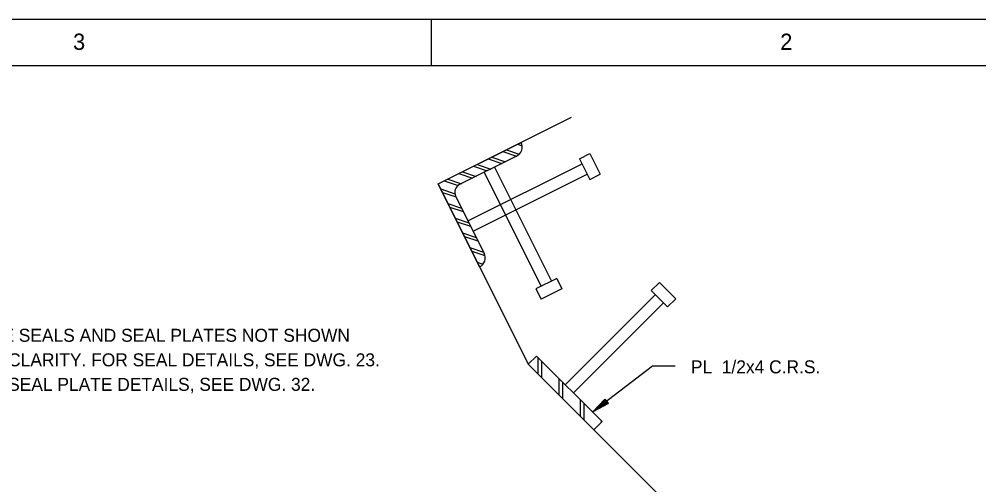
# Model space of a CAD drawing. Extents: x -0.2 to 13.5, y -0.2 to 9.5.
# Drawn here: x 6.602 to 10.051, y 7.66 to 9.333 of the extents above; entities that cross this region are included whole.
import ezdxf

# ---------------------------------------------------------------- set-up
doc = ezdxf.new("R2010")
doc.units = 0
for name, color, linetype in [('Level 1', 7, 'Continuous'), ('Level 2', 7, 'Continuous'), ('Level 25', 7, 'Continuous'), ('Level 3', 7, 'Continuous'), ('Level 36', 7, 'Continuous')]:
    doc.layers.add(name, color=color, linetype=linetype)

msp = doc.modelspace()

# ---------------------------------------------------------------- linework, layer by layer
at = {"layer": 'Level 1'}
msp.add_line((8.0833, 9.1667), (8.0833, 9.3333), dxfattribs=at)
for points in [[(0, 9.3333), (13.3333, 9.3333), (13.3333, 0), (0, 0)], [(0.5, 9.1667), (13.1667, 9.1667), (13.1667, 0.1667), (0.5, 0.1667)]]:
    msp.add_lwpolyline(points, close=True, dxfattribs=at)
at = {"layer": 'Level 2'}
for p, q in [((8.4673, 8.0574), (8.4673, 8.1163)), ((8.4806, 8.0441), (8.4806, 8.103)), ((8.5431, 7.9816), (8.5431, 8.0405)), ((8.5564, 7.9682), (8.5564, 8.0271)), ((8.6189, 7.9057), (8.6189, 7.9646)), ((8.6323, 7.8924), (8.6323, 7.9513)), ((8.6948, 7.8845), (8.6948, 7.8888))]:
    msp.add_line(p, q, dxfattribs=at)
at = {"layer": 'Level 25'}
for p, q in [((8.1077, 8.7411), (8.5876, 8.981)), ((8.1077, 8.7411), (8.5204, 8.9474)), ((8.3935, 8.884), (8.4093, 8.8787)), ((8.3935, 8.884), (8.4093, 8.8787)), ((8.288, 8.8313), (8.337, 8.815)), ((8.288, 8.8313), (8.337, 8.815)), ((8.3005, 8.8375), (8.3494, 8.8212)), ((8.3005, 8.8375), (8.3494, 8.8212)), ((8.3408, 8.8576), (8.3897, 8.8413)), ((8.3408, 8.8576), (8.3897, 8.8413)), ((8.3532, 8.8638), (8.3992, 8.8485)), ((8.3532, 8.8638), (8.3992, 8.8485)), ((8.6155, 8.8319), (8.6528, 8.8506)), ((8.6155, 8.8319), (8.6528, 8.8506)), ((8.2149, 8.6084), (8.6248, 8.8133)), ((8.2149, 8.6084), (8.6248, 8.8133)), ((8.2353, 8.8049), (8.2842, 8.7886)), ((8.2353, 8.8049), (8.2842, 8.7886)), ((8.2478, 8.8111), (8.2967, 8.7948)), ((8.2478, 8.8111), (8.2967, 8.7948)), ((8.3104, 8.8017), (8.5153, 8.3917)), ((8.3104, 8.8017), (8.5153, 8.3917)), ((8.1826, 8.7786), (8.2315, 8.7623)), ((8.1826, 8.7786), (8.2315, 8.7623)), ((8.1951, 8.7848), (8.244, 8.7685)), ((8.1951, 8.7848), (8.244, 8.7685)), ((8.2335, 8.5711), (8.6435, 8.776)), ((8.2335, 8.5711), (8.6435, 8.776)), ((8.2731, 8.783), (8.478, 8.3731)), ((8.2731, 8.783), (8.478, 8.3731)), ((8.6528, 8.7574), (8.69, 8.776)), ((8.6528, 8.7574), (8.69, 8.776)), ((8.1077, 8.7411), (8.4318, 8.0929)), ((8.1077, 8.7411), (8.4318, 8.0929)), ((8.1299, 8.7522), (8.1801, 8.7355)), ((8.1299, 8.7522), (8.1801, 8.7355)), ((8.1423, 8.7584), (8.1913, 8.7421)), ((8.1423, 8.7584), (8.1913, 8.7421)), ((8.1168, 8.7231), (8.1679, 8.706)), ((8.1168, 8.7231), (8.1679, 8.706)), ((8.123, 8.7106), (8.1719, 8.6943)), ((8.123, 8.7106), (8.1719, 8.6943)), ((8.1431, 8.6703), (8.192, 8.654)), ((8.1431, 8.6703), (8.192, 8.654)), ((8.1493, 8.6579), (8.1982, 8.6416)), ((8.1493, 8.6579), (8.1982, 8.6416)), ((8.1695, 8.6176), (8.2184, 8.6013)), ((8.1695, 8.6176), (8.2184, 8.6013)), ((8.1757, 8.6052), (8.2246, 8.5889)), ((8.1757, 8.6052), (8.2246, 8.5889)), ((8.1958, 8.5649), (8.2447, 8.5486)), ((8.1958, 8.5649), (8.2447, 8.5486)), ((8.202, 8.5525), (8.2509, 8.5362)), ((8.202, 8.5525), (8.2509, 8.5362)), ((8.2222, 8.5122), (8.2711, 8.4959)), ((8.2222, 8.5122), (8.2711, 8.4959)), ((8.2284, 8.4998), (8.2756, 8.484)), ((8.2284, 8.4998), (8.2756, 8.484)), ((8.2485, 8.4595), (8.2686, 8.4528)), ((8.2485, 8.4595), (8.2686, 8.4528)), ((8.2547, 8.4471), (8.2602, 8.4453)), ((8.2547, 8.4471), (8.2602, 8.4453)), ((8.5339, 8.401), (8.5526, 8.3638)), ((8.5339, 8.401), (8.5526, 8.3638)), ((8.8737, 8.3581), (8.9032, 8.3875)), ((8.8737, 8.3581), (8.9032, 8.3875)), ((8.9621, 8.3286), (8.9032, 8.3875)), ((8.9621, 8.3286), (8.9032, 8.3875)), ((8.4594, 8.3638), (8.478, 8.3265)), ((8.4594, 8.3638), (8.478, 8.3265)), ((8.9326, 8.2991), (8.8737, 8.3581)), ((8.9326, 8.2991), (8.8737, 8.3581)), ((8.5643, 8.0193), (8.8884, 8.3433)), ((8.5643, 8.0193), (8.8884, 8.3433)), ((8.5938, 7.9898), (8.9179, 8.3139)), ((8.5938, 7.9898), (8.9179, 8.3139)), ((8.9326, 8.2991), (8.9621, 8.3286)), ((8.9326, 8.2991), (8.9621, 8.3286)), ((8.4318, 8.0929), (8.4612, 8.1224)), ((8.4318, 8.0929), (8.4612, 8.1224)), ((8.6969, 7.8867), (8.4612, 8.1224)), ((8.6969, 7.8867), (8.4612, 8.1224)), ((8.4318, 8.0929), (9.4385, 7.0861)), ((8.6675, 7.8572), (8.6969, 7.8867)), ((8.6675, 7.8572), (8.6969, 7.8867))]:
    msp.add_line(p, q, dxfattribs=at)
at = {"layer": 'Level 3'}
for p, q in [((8.6637, 7.9219), (8.6637, 7.9219)), ((8.6775, 7.9325), (8.6775, 7.9325))]:
    msp.add_line(p, q, dxfattribs=at)
for points in [[(8.9594, 8.0856), (8.8776, 8.0856), (8.6637, 7.9219)], [(8.7195, 7.9516), (8.6637, 7.9219), (8.707, 7.968), (8.7177, 7.954), (8.6775, 7.9325), (8.7069, 7.9638), (8.7138, 7.9548), (8.6907, 7.9426), (8.7068, 7.9595), (8.7096, 7.9558), (8.7045, 7.9531)]]:
    msp.add_lwpolyline(points, dxfattribs=at)
at = {"layer": 'Level 36'}
for p, q in [((8.1077, 8.7411), (8.4059, 8.8902)), ((8.1077, 8.7411), (8.4059, 8.8902)), ((8.3896, 8.8413), (8.1846, 8.7388)), ((8.3896, 8.8413), (8.1846, 8.7388)), ((8.6155, 8.8319), (8.6528, 8.7574)), ((8.6155, 8.8319), (8.6528, 8.7574)), ((8.6528, 8.8506), (8.69, 8.776)), ((8.6528, 8.8506), (8.69, 8.776)), ((8.2568, 8.443), (8.1077, 8.7411)), ((8.2568, 8.443), (8.1077, 8.7411)), ((8.1706, 8.6969), (8.2731, 8.4919)), ((8.1706, 8.6969), (8.2731, 8.4919)), ((8.5339, 8.401), (8.4594, 8.3638)), ((8.5339, 8.401), (8.4594, 8.3638)), ((8.5526, 8.3638), (8.478, 8.3265)), ((8.5526, 8.3638), (8.478, 8.3265))]:
    msp.add_line(p, q, dxfattribs=at)
for centre, radius, start, end in [((8.3733, 8.8739), 0.0365, 296.5616, 26.5616), ((8.3733, 8.8739), 0.0365, 296.5616, 26.5616), ((8.1986, 8.7108), 0.0313, 116.5616, 206.5616), ((8.1986, 8.7108), 0.0313, 116.5616, 206.5616), ((8.2405, 8.4756), 0.0365, 296.5616, 26.5616), ((8.2405, 8.4756), 0.0365, 296.5616, 26.5616)]:
    msp.add_arc(centre, radius, start, end, dxfattribs=at)

# ---------------------------------------------------------------- texts
at = {"layer": 'Level 1'}
for s, p in [('3', (6.7956, 9.2231)), ('2', (9.3373, 9.223))]:
    msp.add_text(s, height=0.0584, dxfattribs=at).set_placement(p)
at = {"layer": 'Level 2'}
for s, p in [('GATE SEALS AND SEAL PLATES NOT SHOWN', (6.413, 8.1738)), ('FOR CLARITY. FOR SEAL DETAILS, SEE DWG. 23.', (6.413, 8.0856)), ('PL  1/2x4 C.R.S.', (9.0161, 8.0604)), ('FOR SEAL PLATE DETAILS, SEE DWG. 32.', (6.413, 7.9975))]:
    msp.add_text(s, height=0.046698, dxfattribs=at).set_placement(p)

doc.saveas('drawing.dxf')
